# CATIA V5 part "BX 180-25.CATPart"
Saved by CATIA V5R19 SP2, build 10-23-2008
Part number: BX 180-25
Bounding box of the stored display mesh (mm): x -24.865 to 24.865, y -24.997 to 24.997, z 0 to 135
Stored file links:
  C:\Users\Bora\Desktop\3D Katı model\BX serisi\BX 180\BX 180-25.CATPart
  C:\Program Files\Dassault Systemes\B19\intel_a\reffiles\standard\MetricThickPitch.txt
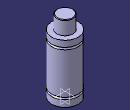
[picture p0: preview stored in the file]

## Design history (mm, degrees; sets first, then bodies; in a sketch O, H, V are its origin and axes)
Body1 (main body)
  Sketch1 on yz-plane, origin (0, 0, 0), H (0, 1, 0), V (0, 0, 1)
    point P1 (25, 16.5)
    point P2 (25, 12.5)
    point P3 (25, 97.5)
    point P4 (25, 93.5)
    point P6 (25, 97.5)
    point P7 (15, 134)
    point P9 (15, 134)
    point P11 (25, 93.5)
    point P12 (25, 16.5)
    point P13 (25, 12.5)
    arc A1 centre (25, 14.5) radius 2 from (25, 16.5) to (25, 12.5) ccw
    arc A2 centre (25, 95.5) radius 2 from (25, 97.5) to (25, 93.5) ccw
    line L1 (25, 109) -> (25, 97.5)
    line L2 (15, 134) -> (15, 109)
    arc A3 centre (14, 134) radius 1 from (15, 134) to (14, 135) ccw
    line L3 (25, 93.5) -> (25, 16.5)
    line L4 (25, 12.5) -> (25, 0)
    line L5 (14, 135) -> (0, 135)
    point P15 (0, 135)
    line L6 (15, 109) -> (25, 109)
    line L7 (25, 0) -> (0, 0)
    tangency: L5 A3
    coincidence: P15 V, P1 P12, P2 P13, P3 P6, P4 P11, P7 P9
    horizontal: L6 H, L7 H
  Shaft1: profile Sketch1, axis Sketch1.V, angle 360
  Sketch2 on face of Shaft1 from Sketch1.L7, origin (0, 0, 0), H (1, 0, 0), V (0, -1, 0)
    point P1 (12.5, 0)
    distance P1 V = 12.5
  Hole1: placed by Sketch2, at (12.5, 0, 0) direction (0, 0, 1), diameter 4.917, depth 6, threaded "M6", thread diameter 6, thread depth 6, pitch 1
  Sketch3 on face of Shaft1 from Sketch1.L7, origin (0, 0, 0), H (1, 0, 0), V (0, -1, 0)
    point P1 (-12.5, 0)
    distance P1 V = 12.5
  Hole2: placed by Sketch3, at (-12.5, 0, 0) direction (0, 0, 1), diameter 4.917, depth 6, threaded "M6", thread diameter 6, thread depth 6, pitch 1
